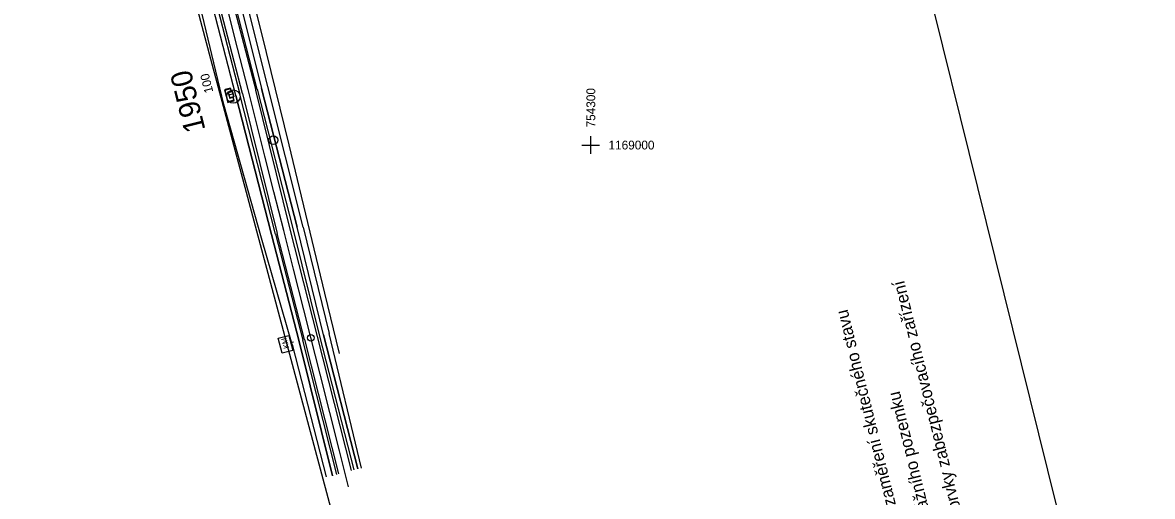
# Model space of a CAD drawing. Extents: x -754679 to -754173, y -1169241 to -1168288.
# Drawn here: x -754428.7 to -754172.8, y -1169079.6 to -1168972.2 of the extents above; entities that cross this region are included whole.
import ezdxf

# ---------------------------------------------------------------- set-up
doc = ezdxf.new("R2010")
doc.units = 0
for name, color, linetype in [('Default', 7, 'Continuous'), ('Vrstva 1', 7, 'Continuous'), ('Vrstva 11', 7, 'Continuous'), ('Vrstva 12', 7, 'Continuous'), ('Vrstva 13', 7, 'Continuous'), ('Vrstva 16', 7, 'Continuous'), ('Vrstva 2', 7, 'Continuous'), ('Vrstva 27', 7, 'Continuous'), ('Vrstva 4', 7, 'Continuous'), ('Vrstva 43', 7, 'Continuous'), ('Vrstva 53', 7, 'Continuous'), ('Vrstva 61', 7, 'Continuous'), ('Vrstva 63', 7, 'Continuous'), ('Vrstva 7', 7, 'Continuous')]:
    doc.layers.add(name, color=color, linetype=linetype)

msp = doc.modelspace()

# ---------------------------------------------------------------- linework, layer by layer
at = {"layer": 'Default'}
for points in [[(-754300, -1169002), (-754300, -1169000), (-754300, -1168998)], [(-754302, -1169000), (-754300, -1169000), (-754298, -1169000)]]:
    msp.add_lwpolyline(points, dxfattribs=at)
at = {"layer": 'Vrstva 1'}
msp.add_line((-754380.95, -1168989.01), (-754380.95, -1168989.01), dxfattribs=at)
for points in [[(-754371.76, -1169010.62), (-754373.81, -1169002.5), (-754376.01, -1168993.77), (-754377.62, -1168987.41), (-754379.98, -1168978.06), (-754382.33, -1168968.78)], [(-754354.86, -1169077.5), (-754356.93, -1169069.33), (-754359.12, -1169060.65), (-754361.33, -1169051.91), (-754363.43, -1169043.59), (-754365, -1169037.37), (-754367.34, -1169028.11), (-754369.54, -1169019.37), (-754371.76, -1169010.62)]]:
    msp.add_lwpolyline(points, dxfattribs=at)
at = {"layer": 'Vrstva 11'}
for p, q in [((-754382.1, -1168988.18), (-754381.86, -1168989.15)), ((-754381.01, -1168988.42), (-754381.98, -1168988.67)), ((-754381.13, -1168987.94), (-754380.89, -1168988.91))]:
    msp.add_line(p, q, dxfattribs=at)
at = {"layer": 'Vrstva 12'}
for p, q in [((-754381.15, -1168987.81), (-754382.14, -1168988.06)), ((-754382.14, -1168988.06), (-754381.78, -1168989.35)), ((-754382.14, -1168988.06), (-754382.11, -1168988.09)), ((-754382.11, -1168988.09), (-754381.18, -1168987.86)), ((-754382.11, -1168988.09), (-754381.76, -1168989.31)), ((-754381.18, -1168987.86), (-754381.15, -1168987.81)), ((-754381.18, -1168987.86), (-754380.87, -1168989.06)), ((-754380.82, -1168989.07), (-754381.15, -1168987.81)), ((-754381.78, -1168989.35), (-754380.82, -1168989.07)), ((-754381.78, -1168989.35), (-754381.76, -1168989.31)), ((-754380.87, -1168989.06), (-754381.76, -1168989.31)), ((-754380.87, -1168989.06), (-754380.82, -1168989.07))]:
    msp.add_line(p, q, dxfattribs=at)
at = {"layer": 'Vrstva 13'}
for p, q in [((-754382.83, -1168987.43), (-754382.97, -1168987.46)), ((-754382.97, -1168987.46), (-754382.21, -1168990.34)), ((-754381.61, -1168987.09), (-754382.83, -1168987.43)), ((-754382.79, -1168987.54), (-754381.57, -1168987.21)), ((-754382.12, -1168990.19), (-754382.79, -1168987.54)), ((-754381.43, -1168987.69), (-754381.61, -1168987.07)), ((-754381.61, -1168987.07), (-754381.61, -1168987.09)), ((-754381.57, -1168987.21), (-754381.58, -1168987.26)), ((-754381.58, -1168987.26), (-754381.47, -1168987.7)), ((-754381.47, -1168987.7), (-754381.43, -1168987.69)), ((-754382.21, -1168990.34), (-754382.07, -1168990.3)), ((-754380.87, -1168989.82), (-754382.12, -1168990.19)), ((-754382.07, -1168990.3), (-754380.83, -1168989.97)), ((-754380.8, -1168989.96), (-754381.01, -1168989.33)), ((-754381.01, -1168989.33), (-754381, -1168989.38)), ((-754381, -1168989.38), (-754380.88, -1168989.81)), ((-754380.88, -1168989.81), (-754380.87, -1168989.82)), ((-754380.83, -1168989.97), (-754380.8, -1168989.96))]:
    msp.add_line(p, q, dxfattribs=at)
at = {"layer": 'Vrstva 16'}
for p, q in [((-754383.09, -1168990.79), (-754389.27, -1168965.03)), ((-754380.4, -1168988.75), (-754386.36, -1168965.6)), ((-754380.26, -1168964.46), (-754374.59, -1168987.21)), ((-754373.15, -1168986.73), (-754378.4, -1168965.63)), ((-754372.32, -1169020.28), (-754380.4, -1168988.75)), ((-754374.59, -1168987.21), (-754366.52, -1169018.6)), ((-754365.15, -1169018.62), (-754373.15, -1168986.73)), ((-754374.58, -1169021.12), (-754383.09, -1168990.79)), ((-754360.51, -1169043.02), (-754366.52, -1169018.6)), ((-754365.15, -1169018.62), (-754359.23, -1169042.75)), ((-754367.66, -1169045.21), (-754374.58, -1169021.12)), ((-754372.32, -1169020.28), (-754366.03, -1169044.49)), ((-754367.66, -1169045.21), (-754359.97, -1169075.19)), ((-754360.51, -1169043.02), (-754352.79, -1169073.4)), ((-754351.91, -1169073.27), (-754359.23, -1169042.75))]:
    msp.add_line(p, q, dxfattribs=at)
msp.add_lwpolyline([(-754358.47, -1169074.96), (-754366.03, -1169044.49)], dxfattribs=at)
at = {"layer": 'Vrstva 4'}
for p, q in [((-754380.4, -1168988.75), (-754386.36, -1168965.6)), ((-754385.5, -1168965.09), (-754379.51, -1168988.47)), ((-754378.9, -1168988.34), (-754384.97, -1168964.92)), ((-754381.82, -1168964.83), (-754375.86, -1168987.58)), ((-754375.55, -1168987.36), (-754381.38, -1168964.7)), ((-754380.26, -1168964.46), (-754374.59, -1168987.21)), ((-754380.4, -1168988.75), (-754372.32, -1169020.28)), ((-754371.4, -1169020.16), (-754379.51, -1168988.47)), ((-754378.9, -1168988.34), (-754371.02, -1169020.06)), ((-754368.08, -1169019.1), (-754375.86, -1168987.58)), ((-754375.55, -1168987.36), (-754367.49, -1169018.94)), ((-754366.52, -1169018.6), (-754374.59, -1168987.21)), ((-754361.88, -1169043.38), (-754368.08, -1169019.1)), ((-754367.49, -1169018.94), (-754361.41, -1169043.35)), ((-754360.51, -1169043.02), (-754366.52, -1169018.6)), ((-754366.03, -1169044.49), (-754372.32, -1169020.28)), ((-754371.4, -1169020.16), (-754365.23, -1169044.2)), ((-754364.82, -1169044.09), (-754371.02, -1169020.06)), ((-754366.03, -1169044.49), (-754358.47, -1169074.96)), ((-754357.5, -1169074.69), (-754365.23, -1169044.2)), ((-754364.82, -1169044.09), (-754357.15, -1169074.54)), ((-754354.18, -1169073.77), (-754361.88, -1169043.38)), ((-754361.41, -1169043.35), (-754353.7, -1169073.61)), ((-754352.79, -1169073.4), (-754360.51, -1169043.02))]:
    msp.add_line(p, q, dxfattribs=at)
at = {"layer": 'Vrstva 43'}
msp.add_circle((-754371.9, -1168998.88), 1, dxfattribs=at)
at = {"layer": 'Vrstva 53'}
for p, q in [((-754378.16, -1168960.13), (-754373.54, -1168979.01)), ((-754373.54, -1168979.01), (-754368.41, -1168999.96)), ((-754368.41, -1168999.96), (-754366.06, -1169009.68)), ((-754366.06, -1169009.68), (-754360.29, -1169033.58)), ((-754360.29, -1169033.58), (-754356.98, -1169047.27))]:
    msp.add_line(p, q, dxfattribs=at)
msp.add_lwpolyline([(-754345.91, -1169130.8), (-754386.06, -1168980.52), (-754394.57, -1168948.26)], dxfattribs=at)
at = {"layer": 'Vrstva 61'}
msp.add_lwpolyline([(-754461.15, -1169240.8), (-754172.83, -1169169.5), (-754273.65, -1168761.78), (-754561.97, -1168833.08)], dxfattribs=at)
at = {"layer": 'Vrstva 63'}
msp.add_line((-754381.05, -1168989.01), (-754380.85, -1168989.01), dxfattribs=at)
msp.add_circle((-754380.95, -1168989.01), 1.51, dxfattribs=at)
at = {"layer": 'Vrstva 7'}
msp.add_line((-754367.34, -1169044.69), (-754367.95, -1169044.84), dxfattribs=at)
msp.add_lwpolyline([(-754367.52, -1169046.53), (-754369.93, -1169047.14), (-754370.78, -1169043.76), (-754368.37, -1169043.15)], close=True, dxfattribs=at)
msp.add_circle((-754363.4, -1169043.69), 0.75, dxfattribs=at)

# ---------------------------------------------------------------- texts
at = {"layer": 'Default'}
msp.add_text('754300', height=2, rotation=90, dxfattribs=at).set_placement((-754299, -1168996))
msp.add_text('1169000', height=2, dxfattribs=at).set_placement((-754296, -1169001))
at = {"layer": 'Vrstva 11'}
msp.add_text('100', height=2, rotation=104.1774, dxfattribs=at).set_placement((-754385.47, -1168987.94))
at = {"layer": 'Vrstva 2'}
msp.add_text('1950', height=4.8, rotation=104.0018, dxfattribs=at).set_placement((-754387.24, -1168996.51))
at = {"layer": 'Vrstva 27'}
for s, p in [('stávající prvky zabezpečovacího zařízení', (-754212.69, -1169096.75)), ('geodetické zaměření skutečného stavu', (-754226.28, -1169100.11)), ('hranice drážního pozemku', (-754219.49, -1169098.43))]:
    msp.add_text(s, height=2.8, rotation=103.9106, dxfattribs=at).set_placement(p)
at = {"layer": 'Vrstva 7'}
msp.add_text('KM', height=1.247, rotation=104.1835, dxfattribs=at).set_placement((-754368.3, -1169045.98))

doc.saveas('drawing.dxf')
